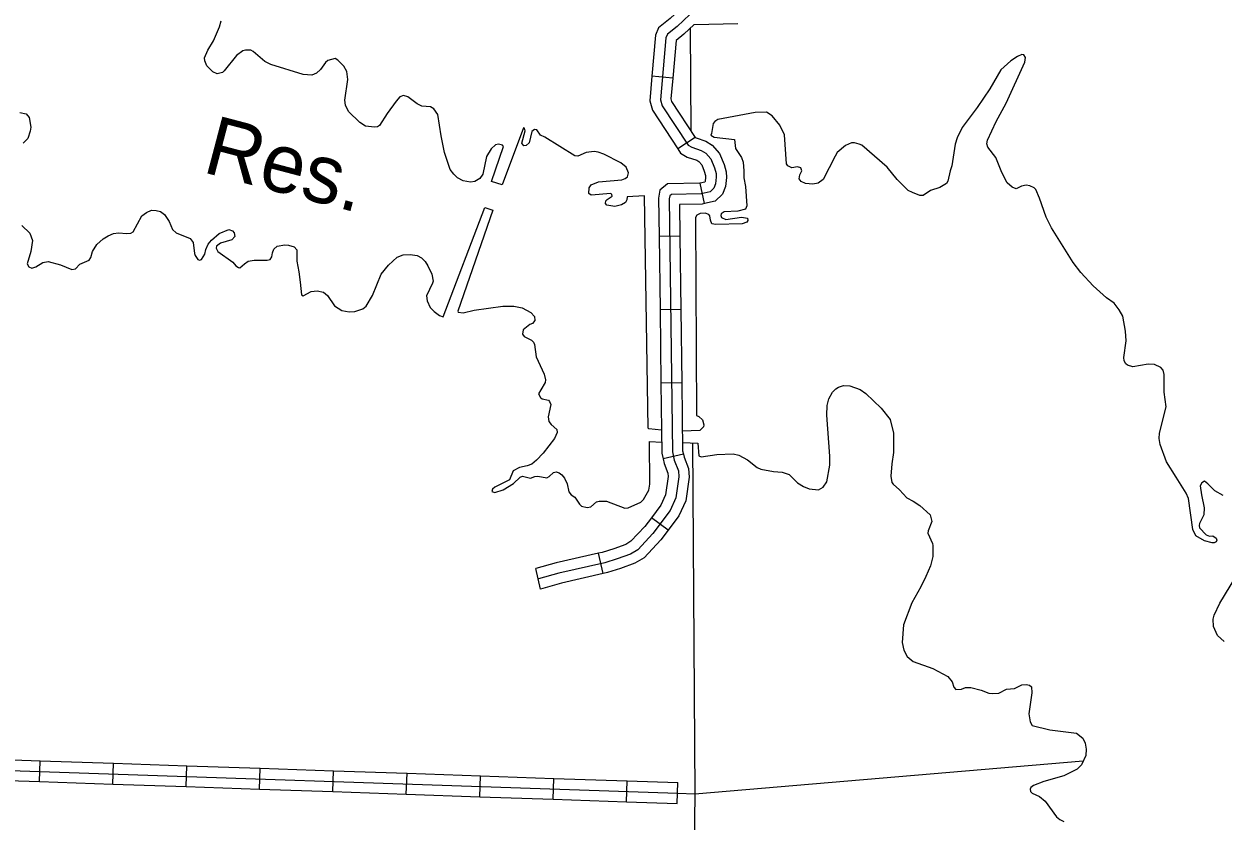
# Model space of a CAD drawing. Extents: x 982240 to 1103002, y 974866 to 1054902.
# Drawn here: x 1028568 to 1037189, y 996650 to 1002381 of the extents above; entities that cross this region are included whole.
import ezdxf

# ---------------------------------------------------------------- set-up
doc = ezdxf.new("R2010")
doc.units = 0
for name, color, linetype in [('32', 7, 'Continuous'), ('35', 7, 'Continuous'), ('5', 7, 'Continuous'), ('9', 7, 'Continuous')]:
    doc.layers.add(name, color=color, linetype=linetype)

msp = doc.modelspace()

# ---------------------------------------------------------------- linework, layer by layer
at = {"layer": '32'}
for p, q in [((1033386.2, 1002376.3), (1033701.6, 1002385.2)), ((1033232.5, 1001991.3), (1033083.1, 1002004.4)), ((1033394.5, 1001564.9), (1033269.1, 1001482.7)), ((1033461.2, 1001089.6), (1033428.7, 1001236.1)), ((1033284.5, 1000855.5), (1033134.5, 1000853.7)), ((1033291.1, 1000327.6), (1033141.1, 1000325.7)), ((1033297.8, 999799.6), (1033147.8, 999797.7)), ((1033309.5, 999287.4), (1033163, 999255.1)), ((1033199.6, 998740.7), (1033079.6, 998830.6)), ((1032733.2, 998429.2), (1032699.5, 998575.3)), ((1032280.9, 998317.9), (1032247.2, 998464.3)), ((1028678.5, 996933.1), (1028683.6, 997083)), ((1029206.1, 996915), (1029211.3, 997065)), ((1029733.8, 996897), (1029739, 997046.9)), ((1030261.5, 996878.9), (1030266.7, 997028.8)), ((1030789.2, 996860.9), (1030794.3, 997010.8)), ((1031316.9, 996842.8), (1031322, 996992.7)), ((1031844.6, 996824.8), (1031849.7, 996974.7)), ((1032372.3, 996806.7), (1032377.4, 996956.6)), ((1032900, 996788.7), (1032905.1, 996938.6)), ((1033264.3, 996776.2), (1033269.4, 996926.1))]:
    msp.add_line(p, q, dxfattribs=at)
for points in [[(1033282.6, 1002484.7), (1033214.1, 1002420.4), (1033130.8, 1002354), (1033108.9, 1002299.9), (1033083.1, 1002004.4)], [(1033356.3, 1002449), (1033264.1, 1002362.6), (1033194.1, 1002306.8), (1033184, 1002281.9), (1033145, 1001835), (1033157, 1001793.1), (1033342.8, 1001509.5), (1033369.3, 1001494), (1033437.9, 1001470.6), (1033469.4, 1001451.2), (1033506.4, 1001410), (1033531.9, 1001347.3), (1033543.9, 1001304.5), (1033546, 1001278.3), (1033540.5, 1001230.6), (1033528.3, 1001199.7), (1033501.6, 1001174), (1033436.1, 1001159.5), (1033223.8, 1001154.5), (1033211, 1001144.2), (1033207.5, 1001123), (1033230.4, 999304.3), (1033243.8, 999243.4), (1033273.6, 999167.8), (1033277.2, 999125.1), (1033255, 998973.7), (1033213.1, 998881.4), (1033090.6, 998718), (1032980.8, 998600.7), (1032928.7, 998569.7), (1032832.4, 998534.3), (1032743.8, 998507.2), (1032414, 998431.2), (1032267.7, 998390.7)], [(1033386.2, 1002376.3), (1033312.3, 1002306.9), (1033256.1, 1002262.1), (1033232.5, 1001991.3)], [(1033083.1, 1002004.4), (1033067.7, 1001827.6), (1033086.7, 1001761), (1033269.1, 1001482.7)], [(1033232.5, 1001991.3), (1033219.5, 1001842.2), (1033224.7, 1001824.1), (1033394.5, 1001564.9)], [(1033394.5, 1001564.9), (1033394.9, 1001564.3), (1033400, 1001561.3), (1033469.5, 1001537.6), (1033517.1, 1001508.4), (1033569.8, 1001449.6), (1033601.7, 1001371.2), (1033616.8, 1001317.4), (1033619.9, 1001277), (1033612.6, 1001212.5), (1033590.9, 1001157.8), (1033537.8, 1001106.6), (1033461.2, 1001089.6)], [(1033269.1, 1001482.7), (1033288.8, 1001452.6), (1033337.3, 1001424.2), (1033405.2, 1001401), (1033420, 1001392), (1033440.7, 1001368.9), (1033459.5, 1001322.6), (1033468.4, 1001291.1), (1033469.2, 1001279.7), (1033465.8, 1001249.3), (1033463.6, 1001243.8), (1033428.7, 1001236.1)], [(1033428.7, 1001236.1), (1033426.8, 1001235.6), (1033196, 1001230.2), (1033140.4, 1001185.3), (1033131, 1001128.8), (1033134.5, 1000853.7)], [(1033461.2, 1001089.6), (1033445, 1001086), (1033281.6, 1001082.2), (1033284.5, 1000855.5)], [(1033134.5, 1000853.7), (1033141.1, 1000325.7)], [(1033284.5, 1000855.5), (1033291.1, 1000327.6)], [(1033141.1, 1000325.7), (1033147.8, 999797.7)], [(1033291.1, 1000327.6), (1033297.8, 999799.6)], [(1033147.8, 999797.7), (1033154.1, 999295.5), (1033163, 999255.1)], [(1033297.8, 999799.6), (1033303.9, 999312.7), (1033309.5, 999287.4)], [(1033163, 999255.1), (1033170.5, 999221), (1033198.4, 999150.2), (1033200.4, 999127.4), (1033181, 998995.5), (1033147, 998920.6), (1033079.6, 998830.6)], [(1033309.5, 999287.4), (1033314.4, 999264.9), (1033346, 999184.8), (1033351.3, 999122.9), (1033326.4, 998952.7), (1033276.8, 998843.6), (1033199.6, 998740.7)], [(1033079.6, 998830.6), (1033032, 998767.1), (1032932.5, 998660.8), (1032895.8, 998638.9), (1032808, 998606.7), (1032724.1, 998581), (1032699.5, 998575.3)], [(1033199.6, 998740.7), (1033147.1, 998670.6), (1033027.4, 998542.8), (1032960.5, 998502.9), (1032855.9, 998464.5), (1032762.9, 998436), (1032733.2, 998429.2)], [(1032699.5, 998575.3), (1032395.2, 998505.3), (1032247.3, 998464.3)], [(1032733.2, 998429.2), (1032432.1, 998359.8), (1032280.9, 998317.9)], [(1028155.9, 997101.1), (1028683.6, 997083)], [(1028683.6, 997083), (1029211.3, 997065)], [(1029211.3, 997065), (1029739, 997046.9)], [(1027904, 997033.2), (1033266.6, 996849.8)], [(1029739, 997046.9), (1030266.7, 997028.8)], [(1030266.7, 997028.8), (1030794.3, 997010.8)], [(1030794.3, 997010.8), (1031322, 996992.7)], [(1031322, 996992.7), (1031849.7, 996974.7)], [(1031849.7, 996974.7), (1032377.4, 996956.6)], [(1028150.8, 996951.1), (1028678.5, 996933.1)], [(1028678.5, 996933.1), (1029206.1, 996915)], [(1029206.1, 996915), (1029733.8, 996897)], [(1029733.8, 996897), (1030261.5, 996878.9)], [(1030261.5, 996878.9), (1030789.2, 996860.9)], [(1032377.4, 996956.6), (1032905.1, 996938.6)], [(1032905.1, 996938.6), (1033269.2, 996926.1)], [(1030789.2, 996860.9), (1031316.9, 996842.8)], [(1031316.9, 996842.8), (1031844.6, 996824.8)], [(1031844.6, 996824.8), (1032372.3, 996806.7)], [(1032372.3, 996806.7), (1032900, 996788.7)], [(1032900, 996788.7), (1033264.1, 996776.2)]]:
    msp.add_lwpolyline(points, dxfattribs=at)
at = {"layer": '5'}
for points in [[(1033356.9, 1002348.4), (1033361.6, 1001611.5)], [(1033375.8, 999368.8), (1033391.9, 996845.5), (1033327.4, 991675.5)], [(1033268.2, 996849.7), (1033391.9, 996845.5), (1036184.7, 997082.4)]]:
    msp.add_lwpolyline(points, dxfattribs=at)
at = {"layer": '9'}
for points in [[(1031178.6, 1001737.8), (1031123.5, 1001651.2), (1031108.7, 1001641.9), (1031087.8, 1001638.4), (1031024.5, 1001646.9), (1030983.8, 1001672.1), (1030901.8, 1001750.4), (1030879.8, 1001796.1), (1030873.9, 1001834), (1030896.5, 1001981.1), (1030888.2, 1002040.1), (1030868.3, 1002077.8), (1030825.2, 1002120.9), (1030805.9, 1002132.5), (1030753.1, 1002118.2), (1030736.4, 1002102.8), (1030700.5, 1002053.8), (1030672.1, 1002026), (1030637.3, 1002013.2), (1030576.1, 1002016.7), (1030343, 1002089.6), (1030300.4, 1002111.6), (1030216.6, 1002183.9), (1030198.4, 1002192.5), (1030161.3, 1002192.7), (1030140.4, 1002188.2), (1030096.1, 1002154), (1030008.5, 1002043.6), (1029994.7, 1002032.2), (1029957.9, 1002022.3), (1029925.5, 1002036.6), (1029882.4, 1002078.8), (1029868.6, 1002115.6), (1029866, 1002137.6), (1029888.9, 1002191.3), (1029930.3, 1002260.5), (1029973.1, 1002359.9), (1029986.2, 1002402.3)], [(1036924, 999006.3), (1036852.2, 999122.1), (1036782.5, 999231.8), (1036736.6, 999357.2), (1036730.6, 999400.2), (1036732.7, 999438.4), (1036779.4, 999627.1), (1036767, 999733.2), (1036765.1, 999859.6), (1036759.3, 999890.5), (1036741.8, 999911.2), (1036697.3, 999931.2), (1036650.1, 999934.2), (1036541.3, 999916.6), (1036502, 999926.7), (1036489.8, 999936.4), (1036479.3, 999958.3), (1036475.7, 999982.3), (1036493, 1000102.1), (1036488.4, 1000172.2), (1036468.8, 1000280.1), (1036442.8, 1000325.7), (1036405.6, 1000373), (1036352.6, 1000410.9), (1036255.4, 1000498.9), (1036167.1, 1000593.2), (1036111.3, 1000665.1), (1035955.3, 1000915.3), (1035917.4, 1000992.7), (1035869.2, 1001129.1), (1035842.8, 1001189.7), (1035831.4, 1001203.4), (1035800.1, 1001216.8), (1035772.9, 1001222.1), (1035741, 1001214.4), (1035701.4, 1001196.4), (1035672, 1001207.7), (1035638.3, 1001239.1), (1035599.5, 1001312.4), (1035554.9, 1001420.8), (1035497.1, 1001495.7), (1035490.6, 1001518.6), (1035495, 1001544.8), (1035559, 1001678.7), (1035631.1, 1001811.9), (1035763.5, 1002107), (1035768.8, 1002140.2), (1035756.3, 1002158), (1035743.2, 1002160.7), (1035711.5, 1002147.9), (1035664.1, 1002115.7), (1035590.5, 1002051.8), (1035511.5, 1001913.4), (1035421.4, 1001780.9), (1035314.5, 1001635.9), (1035277.2, 1001562.8), (1035262.2, 1001516.3), (1035238.7, 1001361.2), (1035228.5, 1001324.8)], [(1032313.9, 1001567.6), (1032282.2, 1001582), (1032256.4, 1001618.5), (1032238.2, 1001622.1), (1032220.5, 1001607.7), (1032199.4, 1001525.9), (1032179.8, 1001507.4), (1032160.8, 1001504.9), (1032148.3, 1001524.7), (1032172.3, 1001612.6), (1032166.9, 1001631.5), (1032159.8, 1001634.3), (1032005, 1001223.3), (1031928.3, 1001248.6), (1032015.7, 1001499.5), (1032008.4, 1001508.4), (1031979.2, 1001515.7), (1031959.3, 1001511.2), (1031927.9, 1001483.4), (1031894.1, 1001428.4), (1031867, 1001300.4), (1031844.6, 1001269.7), (1031809, 1001248.8), (1031779.1, 1001243.1), (1031726.8, 1001253.9), (1031686.2, 1001274.1), (1031658.6, 1001300.5), (1031632.7, 1001335), (1031591.8, 1001457.5), (1031567, 1001577.3), (1031542.5, 1001730.3), (1031515.5, 1001769.8), (1031490.1, 1001784.2), (1031427.9, 1001790.8), (1031395.4, 1001807.1), (1031327.2, 1001857.7), (1031295.9, 1001866), (1031271.1, 1001856.4), (1031243.7, 1001825.6), (1031178.6, 1001737.8)], [(1028539.3, 1001745), (1028584.6, 1001735), (1028605.3, 1001707.4), (1028616.9, 1001639.4), (1028613.5, 1001610.2), (1028595.7, 1001557.6), (1028562.4, 1001524.8)], [(1034399.6, 1001430.1), (1034314.9, 1001262), (1034278.5, 1001236.1), (1034240.6, 1001228.2), (1034186.4, 1001232.9), (1034156, 1001247.3), (1034142.5, 1001268), (1034146.9, 1001296.2), (1034161.2, 1001323.7), (1034152.7, 1001346.5), (1034128.5, 1001354), (1034089.6, 1001347.1), (1034059.2, 1001361.4), (1034050.9, 1001375.3), (1034035.1, 1001582.6), (1034002.4, 1001653.1), (1033947.7, 1001720.1), (1033907.1, 1001746.2), (1033825, 1001744.3), (1033556.6, 1001693.8), (1033534.9, 1001680.3), (1033524.2, 1001665), (1033510.9, 1001592.4), (1033506.1, 1001581.3), (1033530.5, 1001565.8), (1033676.1, 1001550.1), (1033683.7, 1001485.1), (1033728.2, 1001420.9), (1033740, 1001387.1), (1033744.5, 1001323.9), (1033744.6, 1001273.8)], [(1032866.7, 1001260.2), (1032891.5, 1001269.8), (1032907.3, 1001282.2), (1032913.6, 1001311.5), (1032896.7, 1001350.2), (1032858.9, 1001382.4), (1032736.2, 1001444.8), (1032696.8, 1001458.9), (1032667.6, 1001463.2), (1032610.7, 1001455.9), (1032551.2, 1001430.4), (1032529.1, 1001431.9), (1032313.9, 1001567.6)], [(1034592.2, 1001508.2), (1034572.9, 1001517.6), (1034540.6, 1001526.8), (1034518.6, 1001525.3), (1034473.9, 1001507.2), (1034414, 1001456.6), (1034399.6, 1001430.1)], [(1035228.5, 1001324.8), (1035210.2, 1001250.1), (1035200.6, 1001233.8), (1035152.1, 1001205.6), (1035085.5, 1001184), (1035034.3, 1001147.7), (1035008.2, 1001148.1), (1034956.7, 1001167.9), (1034926.2, 1001184.3), (1034847.3, 1001262.7), (1034775.1, 1001352.3), (1034592.2, 1001508.2)], [(1033744.6, 1001273.8), (1033756.5, 1001213.3)], [(1033152, 999460.7), (1033061.2, 999469.5), (1033055.1, 999473.4), (1033029.6, 1001144.6), (1032904.6, 1001138.7), (1032903.1, 1001116.5), (1032893.5, 1001098.3), (1032864.8, 1001079.5), (1032817, 1001068.4), (1032759.7, 1001079.1), (1032749.4, 1001089.9), (1032752, 1001108), (1032761.7, 1001119.3), (1032797.3, 1001143.2), (1032794, 1001155.1), (1032786.8, 1001161), (1032646.8, 1001149.7), (1032630.5, 1001161.3), (1032630.6, 1001203.5), (1032645.1, 1001223.9), (1032699.7, 1001245.2), (1032866.7, 1001260.2)], [(1033756.5, 1001213.3), (1033766.2, 1001074.1), (1033755.7, 1001049.7), (1033699.8, 1001034.2), (1033601.7, 1001029.9), (1033582, 1001015.4), (1033577.3, 1001004.2), (1033582.6, 1000990.3), (1033615, 1000976), (1033727.8, 1000991.7), (1033769.1, 1000983.7), (1033771.5, 1000966.6), (1033765.7, 1000956.5), (1033733, 1000942.7), (1033541.7, 1000938.2), (1033514.5, 1000943.6), (1033503.9, 1000970.4), (1033499.2, 1001000.4), (1033492.9, 1001011.3), (1033466.7, 1001020.7), (1033429.7, 1001017.9), (1033405.9, 1001006.3), (1033396.3, 1000990), (1033403.8, 999565)], [(1029060.6, 1000744), (1029092.5, 1000795.9), (1029137.7, 1000835.1), (1029174.2, 1000858.1), (1029211.9, 1000874), (1029246.9, 1000879.8), (1029307.1, 1000873.2), (1029335.1, 1000875.9), (1029352.9, 1000887.3), (1029415.4, 1001000.2), (1029447.9, 1001025), (1029484.6, 1001041.9), (1029517.7, 1001040.7), (1029548.9, 1001033.4), (1029578.4, 1001012), (1029611.6, 1000961.6), (1029635, 1000903), (1029662.6, 1000879.5), (1029762.8, 1000837.7), (1029784.5, 1000809.1), (1029793.3, 1000730), (1029799.6, 1000716.1), (1029818.4, 1000686.5), (1029829.5, 1000681.7), (1029843.4, 1000686.1), (1029867.5, 1000726.8), (1029874.8, 1000759), (1029892.9, 1000797.6), (1029916.3, 1000826.2), (1029972.3, 1000873.7), (1030039.8, 1000903.4), (1030068.1, 1000893), (1030079.4, 1000878.2), (1030084, 1000852.2), (1030063.6, 1000827.7), (1029981, 1000803.7), (1029952.4, 1000783.9), (1029949.7, 1000769.8), (1029961.3, 1000744), (1030070.3, 1000667.3), (1030090.9, 1000642.7), (1030109.2, 1000630.1), (1030120.2, 1000628.3), (1030153.6, 1000657.2), (1030179.3, 1000674.9), (1030222.2, 1000681.9), (1030315.3, 1000683.1), (1030337.3, 1000687.6), (1030350.9, 1000706), (1030354.2, 1000734.1), (1030364.6, 1000761.5), (1030389.2, 1000783.1), (1030444, 1000793.4), (1030470.1, 1000791), (1030509.5, 1000777.9), (1030529, 1000757.3), (1030530.9, 1000674.1), (1030544.7, 1000599.1), (1030553.4, 1000525.1), (1030563.5, 1000433), (1030574.7, 1000427.2), (1030633.1, 1000456.7), (1030677.1, 1000461.7), (1030721.4, 1000451.7)], [(1030721.4, 1000451.7), (1030751, 1000429.3), (1030799.8, 1000355.2), (1030852.6, 1000321.3), (1030907, 1000310.6), (1030946, 1000312.5), (1031004.7, 1000332.9), (1031028.2, 1000352.5), (1031074.6, 1000427.9), (1031136.2, 1000581.8), (1031187.8, 1000646.3), (1031250.6, 1000702.9), (1031295.2, 1000722), (1031344.3, 1000724.2), (1031394.6, 1000715.3), (1031426, 1000700), (1031452.7, 1000672.5), (1031472.4, 1000641.9), (1031499.8, 1000581.3), (1031509, 1000532.4), (1031505.3, 1000517.2), (1031461.4, 1000424.9), (1031466.2, 1000388.9), (1031487.3, 1000342.2), (1031516.1, 1000312.8), (1031554.8, 1000283.6), (1031581.1, 1000274.2), (1031881.5, 1001061.9), (1031938, 1001043.1), (1031686.3, 1000315.7), (1031690.5, 1000307.8), (1031726.6, 1000304.6), (1031803.7, 1000322.8)], [(1028553, 1000931.5), (1028610.4, 1000876.6), (1028628.6, 1000823.9), (1028617.5, 1000744.3), (1028591.5, 1000655.4), (1028604, 1000633.6), (1028624.2, 1000625.1), (1028652.1, 1000633.8), (1028704.4, 1000665.1), (1028741.3, 1000673), (1028831.5, 1000648.6)], [(1028831.5, 1000648.6), (1028911.3, 1000616.1), (1028939.3, 1000620.8), (1028969.6, 1000652.6), (1029037, 1000683.3), (1029047.6, 1000700.6), (1029060.6, 1000744)], [(1031803.7, 1000322.8), (1032011, 1000352.7), (1032090.1, 1000351.5), (1032150.5, 1000339.9), (1032213.4, 1000306.2), (1032238.1, 1000276.7), (1032240.8, 1000247.7), (1032224.2, 1000228.2), (1032204.4, 1000218.7), (1032157.2, 1000180.5), (1032152.9, 1000149.3), (1032163.3, 1000134.5), (1032217, 1000106.6), (1032231.3, 1000092.9), (1032237.7, 1000077), (1032251.8, 999988), (1032308.8, 999861.9), (1032316.7, 999822), (1032315.2, 999801.9), (1032284.3, 999751), (1032267, 999721.5), (1032281.6, 999695.7), (1032294.8, 999686), (1032338.2, 999675), (1032347.4, 999666.2), (1032355.9, 999645.3), (1032336.9, 999555.5), (1032341.6, 999523.5), (1032359.2, 999500.9), (1032398.1, 999464.6), (1032402.6, 999442.7)], [(1033957.9, 999161.9), (1034019.1, 999158.3), (1034068.6, 999140.4), (1034129, 999082.6), (1034171.7, 999055.5), (1034213.2, 999038.4), (1034280.5, 999031.9), (1034314.1, 999050.8), (1034340.2, 999089.5), (1034362.6, 999207.5), (1034363.1, 999272.7), (1034340.3, 999567.2), (1034343.7, 999636.5), (1034355.6, 999686), (1034381.5, 999732.7), (1034405, 999757.4), (1034423.8, 999768.8), (1034461.6, 999780.8), (1034506.7, 999777.8), (1034581.4, 999753.5), (1034621.2, 999723.3), (1034731.8, 999619.5), (1034794.8, 999536.7), (1034820.1, 999438.9), (1034820.3, 999299.5), (1034807.2, 999216.9), (1034801.2, 999129.4), (1034808.2, 999084.4), (1034818.5, 999071.6), (1034862.7, 999031.7)], [(1033403.8, 999565), (1033403.8, 999565), (1033421, 999559.4), (1033445.6, 999533.8), (1033455.4, 999499), (1033454.8, 999484.9), (1033427.3, 999458.2), (1033302.8, 999453.8)], [(1032402.6, 999442.7), (1032383.6, 999399.1), (1032301.8, 999294.8), (1032253.9, 999243.5), (1032219.5, 999216.6), (1032186.7, 999203.8), (1032131.9, 999191.5), (1032084.3, 999168.3), (1032058.8, 999102.5), (1031952.8, 999049.8), (1031936.1, 999036.4), (1031932.5, 999018.2), (1031953.7, 999012.7), (1032012.3, 999032.2), (1032086.5, 999077), (1032135.5, 999122.3), (1032151.4, 999129.7), (1032210.8, 999116.1), (1032241.6, 999126.8), (1032263.6, 999128.3), (1032328, 999117.8), (1032343.8, 999126.2), (1032375.2, 999156), (1032394.1, 999159.5), (1032416.3, 999154), (1032435.7, 999139.4), (1032454.2, 999115.7), (1032473.2, 999075), (1032485.6, 999016.1), (1032501.1, 998995.4), (1032528.5, 998979), (1032561.8, 998927.6), (1032577.1, 998913.9), (1032618.4, 998903.8), (1032643.3, 998908.4), (1032684.6, 998945.5), (1032702.5, 998950), (1032756.6, 998949.2), (1032887, 998898.1), (1032912, 998900.7), (1033002.2, 998941.9), (1033021.8, 998960.4), (1033060.4, 999027.6), (1033068.4, 999071.9), (1033065.3, 999378.9), (1033153.1, 999374.3)], [(1033303.2, 999372.6), (1033412.2, 999366.9), (1033420.3, 999274.7), (1033437.5, 999268.1), (1033549.3, 999284.8), (1033667.4, 999289.5), (1033706.7, 999279.4), (1033769.6, 999247.8), (1033839, 999192.2), (1033865.3, 999180.8), (1033957.9, 999161.9)], [(1037189.9, 998989.5), (1037130, 999024.2), (1037079.7, 999074.2), (1037055.2, 999092.7), (1037036.5, 999081.2), (1037025.9, 999059.9), (1037035.4, 998995.9), (1037054.7, 998901), (1037051.8, 998851.8), (1037020.1, 998789.8), (1037017.5, 998773.7), (1037020.9, 998757.7), (1037067.1, 998708.6), (1037091.4, 998698.2), (1037115.4, 998699.7), (1037140.8, 998683.3), (1037144.2, 998668.3), (1037139.4, 998657.1), (1037126.6, 998649.8), (1037110.5, 998649.4), (1037055.1, 998663.2), (1036994.2, 998699.9), (1036971.1, 998746.5), (1036941.9, 998967.6), (1036924, 999006.3)], [(1034862.7, 999031.7), (1034914.8, 998972.6), (1034960.4, 998948.6), (1035008.2, 998918.6), (1035082.8, 998852.1), (1035095, 998802.3), (1035068.5, 998735.4), (1035067.9, 998720.3), (1035100.6, 998645.9), (1035103, 998629.9), (1035102.8, 998550.6), (1035085.3, 998483.9), (1035053, 998406.9), (1035015.6, 998333.6)], [(1037198, 997940), (1037150, 997983.1), (1037121.4, 998048.6), (1037119.2, 998101.8), (1037124.5, 998130), (1037165.6, 998215.2), (1037282.5, 998405.6)], [(1035015.6, 998333.6), (1034951.5, 998219.6), (1034892, 998060.7), (1034882.9, 997934), (1034893.3, 997877.1), (1034919.3, 997832.5), (1034961.3, 997796.4), (1035102.7, 997745.5), (1035211.2, 997688.9), (1035242.1, 997650.4), (1035254, 997612.6), (1035268.4, 997595.9), (1035309.5, 997597.8), (1035338.2, 997609.5)], [(1035338.2, 997609.5), (1035375.3, 997610.4), (1035450.9, 997590.1), (1035505.5, 997568.3), (1035532.6, 997565.9), (1035577.6, 997570), (1035633.1, 997597.4), (1035691.1, 997601.7), (1035742.6, 997628), (1035773.5, 997631.8), (1035796.7, 997626.3), (1035811, 997613.6), (1035815, 997570.5), (1035793.4, 997420.5), (1035802.8, 997362.5), (1035816.4, 997335.7)], [(1035816.4, 997335.7), (1035943.2, 997304.6), (1036136.1, 997281.4), (1036181, 997246.4), (1036199, 997208.7), (1036206.1, 997165.8), (1036203.2, 997120.6), (1036171.8, 997054.6), (1036140.5, 997022.7), (1036043.6, 996974), (1035901.3, 996933.3), (1035826.9, 996906.3), (1035808.2, 996891.8), (1035802.5, 996879.6), (1035805.9, 996862.7), (1035817.2, 996850.9), (1035869.9, 996827.2), (1035910.9, 996792.1), (1035991.8, 996680.8), (1036015.3, 996661.3), (1036044.8, 996646)]]:
    msp.add_lwpolyline(points, dxfattribs=at)

# ---------------------------------------------------------------- texts
at = {"layer": '35'}
msp.add_text('Res.', height=422.4, rotation=345.27442, dxfattribs=at).set_placement((1029842.1, 1001317.8))

doc.saveas('drawing.dxf')
